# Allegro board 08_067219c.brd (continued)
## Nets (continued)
UNNAMED_17_ICM24512_I159_SCL: A1.6 R61.1
UNNAMED_17_ICM24512_I159_SDA: A1.5 R62.1
UNNAMED_18_7404V6_I276_Y: R135.1 U15.4
UNNAMED_18_ADAU1701_I166_ADCRES: R109.2(N2) U10.3
UNNAMED_18_ADAU1701_I166_CM: C102.1 C104.1 U10.40
UNNAMED_18_ADAU1701_I166_DVDD: C106.P C107.1 C109.1 Q2.3 U10.13 U10.24
UNNAMED_18_ADAU1701_I166_FILTA: C98.1 C100.1 U10.47
UNNAMED_18_ADAU1701_I166_FILTD: C111.1 C113.1 U10.41
UNNAMED_18_ADAU1701_I166_MP6: R110.2(N2) U10.15
UNNAMED_18_ADAU1701_I166_PLLLF: C108.1 C110.1 U10.35
UNNAMED_18_ADAU1701_I166_RESETB: C78.2(N2) R44.1 U10.5
UNNAMED_18_ADAU1701_I166_VDRIVE: Q2.1 R112.1 U10.17
UNNAMED_18_CAP_I169_N2: C108.2(N2) R111.1
UNNAMED_18_CAP_I344_N1: C80.1 P2.2 R51.1
UNNAMED_18_CN2P_I318_N1: P22.1 R113.1
UNNAMED_18_CN10P_I337_N1: P2.1 R77.1
UNNAMED_18_CN10P_I337_N3: P2.3 R78.1
UNNAMED_18_CN10P_I337_N4: P2.4 P44.1(N1) R117.1
UNNAMED_18_CN10P_I337_N5: P2.5 R79.1
UNNAMED_18_CN10P_I337_N6: P2.6 P43.1(N1) R125.1
UNNAMED_18_CN10P_I337_N7: P2.7 R80.1
UNNAMED_18_CN10P_I337_N8: P2.8 R81.1
UNNAMED_18_CN10P_I337_N9: P2.9(N9) R82.1
UNNAMED_18_DIOLED_I280_P: DS4.A(P) R135.2(N2)
UNNAMED_19_CAP_I7_N1: C123.1 R124.2(N2)
UNNAMED_19_CAP_I17_N1: A2.8 C115.1 L17.1 R124.1
UNNAMED_19_CAP_I17_N2: A2.9 C115.2(N2)
UNNAMED_19_CAP_I20_N1: A2.13 C118.1 C122.2(N2) L16.1
UNNAMED_19_CAP_I20_N2: A2.12 C118.2(N2)
UNNAMED_19_CAP_I21_N1: C122.1 R123.2(N2)
UNNAMED_19_CAP_I26_N1: A2.22 C114.1
UNNAMED_19_CAP_I26_N2: A2.23 C114.2(N2) C119.2(N2) L14.1
UNNAMED_19_CAP_I28_N1: A2.18 C121.1
UNNAMED_19_CAP_I28_N2: A2.19 C121.2(N2) L15.1 R122.1
UNNAMED_19_CAP_I32_N2: C129.2(N2) L17.2(N2) P48.1(N1)
UNNAMED_19_CAP_I33_N1: C128.1 L16.2(N2) P47.1(N1)
UNNAMED_19_CAP_I38_N2: C127.2(N2) L15.2(N2) P46.1(N1)
UNNAMED_19_CAP_I40_N1: C120.1 R122.2(N2)
UNNAMED_19_CAP_I42_N1: C119.1 R121.2(N2)
UNNAMED_19_CAP_I44_N1: C126.1 L14.2(N2) P45.1(N1)
UNNAMED_19_CAP_I49_N1: A2.16 C130.1
UNNAMED_19_CAP_I51_N1: A2.6 C90.1 R116.1
UNNAMED_19_CAP_I55_N1: A2.17 C124.1
UNNAMED_19_DIOLED_I16_N: A2.24 DS6.C
UNNAMED_19_DIOLED_I16_P: DS6.A(P) R115.2(N2)
UNNAMED_19_ICBD28623MUV_I18_BCLK: A2.3 R119.2(N2)
UNNAMED_19_ICBD28623MUV_I18_GAIN: A2.5 R83.1 R114.2(N2)
UNNAMED_19_ICBD28623MUV_I18_LRCLK: A2.4 R120.2(N2)
UNNAMED_19_ICBD28623MUV_I18_SDATA: A2.2 R118.2(N2)
USBI_SCL: R77.2(N2) R137.2(N2) U14.4
USBI_SDA: R78.2(N2) R136.2(N2) U12.4
VOUT0: U10.46
VOUT1: U10.45
VOUT2: R89.1 U10.44
VOUT3: R90.1 U10.43(VOUT3)

Pads without a net: U10 31; U15 1

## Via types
v1: diameter 0.508, hole 0.254, TOP to BOTTOM, 1342 vias

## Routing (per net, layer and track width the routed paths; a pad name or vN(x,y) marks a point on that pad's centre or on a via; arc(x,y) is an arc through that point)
DGND: length 1006.2
  TOP w0.203: U10.38 39.39,84.03 C102.2 39.19,84.3 39.42,84.53 U10.37 v1(42.11,84.53) ; C105.2 44.44,87.54 43.74,86.84 U10.33 ; C23.1 43.12,44.31 43.12,45.92 44.2,46.99 U7.30 v1(44.2,50.02) ; v1(45.59,57.02) 45.7,56.92 U7.4 45.7,54.58 v1(45.21,54.09) ; 42.04,48.13 42.2,48.3 U7.26 ; U10.42 39.99,82.03 39.25,81.29 C113.2 ; 47.37,56.9 47.2,56.73 U7.1 47.2,55.52 47.18,55.5 47.18,55.36 v1(46.92,55.11) ; v1(45.47,84.58) 45.24,84.81 U10.30 ; v1(46.99,53.15) 47.16,53.32 U7.44 ; U14.3 v1(62.84,89.01) ; U12.3 v1(62.9,84.31) ; U2.5 14.86,42.84 14.86,42.24 14.66,42.04 v1(14.1,42.04) ; U10.20 50.55,82.53 C99.2 ; U10.7 45.24,76.42 v1(45.47,76.2) ; v1(46.99,50.42) 47.4,50.42 47.5,50.32 U7.38 ; U7.10 42.7,55.34 42.93,55.12 v1(43.1,55.12) ; 52.57,114.74 53.07,115.24 A2.11 ; 52.57,114.74 A2.15 ; 52.57,114.74 v1(52.32,114.49) 52.07,114.74 A2.21 ; 46.14,44.23 46.14,46.05 45.2,46.99 U7.32 v1(45.2,50.02) ; U13.4 18.44,97.91 17.94,98.41 ; U10.1 42.24,78.53 42.04,78.74 v1(42.04,78.75) ; U10.12 v1(48.34,77.6) ; U7.20 v1(41.9,51.82) ; U10.25 v1(48.48,85.96)
  TOP w0.254: v1(11.3,21.72) 11.12,21.53 U8.6
  TOP w0.508: C12.1 55.49,60.96 ; C12.1 54.23,59.91 ; C12.1 52.97,60.96 ; C12.1 54.23,62.01 ; P42.1 8.76,41.31 ; P42.1 7.58,40.13 ; P42.1 8.76,38.95 ; 5.17,23.24 C25.1 ; C25.1 6.22,24.5 ; C25.1 7.28,23.24 ; C25.1 6.22,21.98 ; C107.2 v1(50.8,77.27) ; C107.2 50.22,78.03 ; C107.2 51.38,78.03 ; P40.1 8.76,32.93 ; P40.1 8.76,30.57 ; P40.1 7.58,31.75 ; P40.1 9.94,31.75 ; 40.48,87.63 C103.2 ; C103.2 41.03,87.05 ; C103.2 v1(41.03,88.42) ; R3.1 v1(16.56,38.61) ; R3.1 15.87,39.23 ; R3.1 15.87,37.99 ; C97.N 35.06,87.63 ; C97.N 31.96,87.63 ; C97.N 33.51,86.58 ; C97.N 33.51,88.68 ; 21.4,31.75 C40.1 ; C40.1 22.23,32.91 ; C40.1 22.23,30.59 ; C40.1 23.06,31.75 ; P1.2 34.49,71.48 ; P1.2 34.49,69.11 ; P1.2 35.67,70.29 ; P1.2 33.31,70.29 ; 10.38,59.69 P39.1 ; P39.1 11.56,60.87 ; P39.1 12.74,59.69 ; P39.1 11.56,58.51 ; P21.6 P21.8 59.44,4.78 59.44,6.1 ; 6.25,50.66 C131.1 ; C131.1 7.07,51.82 ; C131.1 5.42,51.82 ; C131.1 6.25,52.97 ; 61.42,112.15 C123.2 ; C123.2 v1(62.23,112.9) ; C123.2 61.42,113.65 ; P1.16 53.45,70.29 ; P1.16 52.27,69.11 ; P1.16 52.27,71.48 ; P1.16 51.09,70.29 ; C79.2 v1(32.85,65.02) ; 29.58,5.28 P27.1 29.58,7.38 ; C65.2 42.37,29.46 ; C65.2 41.78,30 ; C65.2 41.2,29.46 ; C69.2 75.39,85.48 ; C69.2 74.22,85.48 ; C69.2 74.8,84.93 ; P41.1 78.65,38.1 ; P41.1 76.29,38.1 ; P41.1 77.47,36.92 ; P41.1 77.47,39.28 ; P7.1 2.4,118.59 ; P7.1 v1(4.06,116.94) ; P7.1 2.4,115.29 ; 61.25,67.75 P1.23 ; P1.23 62.43,66.57 ; P1.23 62.43,68.94 ; P1.23 63.61,67.75 ; 49.45,25.76 C93.1 ; C93.1 50.62,25.76 ; C93.1 v1(50.04,26.54) ; C62.2 42.24,40 ; C62.2 41.66,40.54 ; C62.2 41.07,40 ; v1(56.13,105.79) C90.2 R42.1 v1(57.15,105.79) ; 46.74,74.8 C78.1 46.01,75.55 ; 37.03,69.11 P1.4 ; P1.4 38.21,70.29 ; P1.4 35.85,70.29 ; P1.4 37.03,71.48 ; C36.1 16.38,50.56 ; C36.1 17.18,49.28 ; C36.1 16.38,47.99 ; P18.2 61.86,81 ; P18.2 63.04,79.82 ; P18.2 61.86,78.64 ; P18.2 60.68,79.82 ; P1.12 47.19,71.48 ; P1.12 48.37,70.29 ; P1.12 46.01,70.29 ; P1.12 47.19,69.11 ; C42.1 v1(14.44,35.18) ; C42.1 15.13,35.76 ; C42.1 15.13,34.59 ; R100.1 54.41,50.6 54.41,49.96 v1(54.23,49.78) ; R100.1 55.24,50.67 ; R100.1 R101.1 55.24,51.82 ; v1(9.16,111.63) C56.2 ; C56.2 9.74,112.4 ; C56.2 8.57,112.4 ; 55.36,74.8 C106.N ; C106.N 58.46,74.8 ; C106.N 56.91,75.86 ; C106.N 56.91,73.75 ; 50.01,9.6 P21.10 ; P21.10 51.16,10.76 ; P21.10 51.16,8.44 ; P21.10 52.32,9.6 ; C126.2 v1(29.72,109.34) ; C126.2 30.92,108.28 ; C126.2 30.92,110.39 ; v1(7.36,87.25) C84.2 ; P5.4 43.86,95.75 ; P5.4 42.68,96.93 ; P5.4 42.68,94.57 ; P5.4 41.5,95.75 ; R5.1 65.96,76.45 ; R5.1 v1(65.39,77.23) ; R5.1 65.39,75.83 ; 36.96,6.1 36.96,4.78 P27.8 P27.6 ; P1.6 39.57,71.48 ; P1.6 39.57,69.11 ; P1.6 40.75,70.29 ; P1.6 38.39,70.29 ; C1.1 12.59,42.14 ; C1.1 v1(9.78,42.14) ; C1.1 11.43,42.97 ; 62.82,86.41 C133.2 ; C133.2 v1(62.82,87.76) ; C133.2 62.27,87 ; C96.N 58.46,87.63 ; C96.N 55.36,87.63 ; C96.N 56.91,86.58 ; C96.N 56.91,88.68 ; 80.64,90.3 A1.4 ; A1.4 81.98,89.74 ; A1.4 81.98,90.86 ; A1.4 v1(83.57,90.3) ; C113.2 v1(39.12,80.53) ; v1(17.17,99.06) C74.2 17.94,98.41 ; 71.46,66.7 DS4.C ; DS4.C 72.26,67.58 ; DS4.C 73.28,66.7 v1(73.28,66.67) ; DS4.C 72.26,65.83 ; 52.37,121.4 C130.2 ; C130.2 v1(52.96,122.15) ; C130.2 53.54,121.4 ; 14.47,58.41 R49.1 15.04,57.78 ; 67.97,66.98 C135.2 ; C135.2 67.97,68.15 ; C135.2 v1(67.18,67.56) ; P2.10 76.11,47.68 ; P2.10 73.87,47.68 ; P2.10 74.99,48.8 ; P2.10 74.99,46.56 ; C3.1 v1(31.5,58.93) ; C44.2 v1(58.16,31.98) ; C64.2 31.48,47.27 ; C64.2 30.9,46.73 ; C64.2 32.07,46.73 ; 12.23,34.7 DS5.C ; DS5.C 13.93,34.7 ; DS5.C v1(13.08,35.75) ; DS5.C 13.08,33.84 ; 38.79,25.76 C31.2 ; C31.2 39.95,25.76 ; C31.2 v1(39.37,26.54) ; C75.2 v1(16.54,93.09) ; 52.06,7.38 P21.1 52.06,5.28 ; C98.2 v1(39.12,77.77) ; R48.1 v1(17.91,42.04) ; TP10.1 81.95,43.81 ; TP10.1 80.77,45 ; TP10.1 79.59,43.81 ; TP10.1 80.77,42.63 ; 58.71,70.29 P1.22 ; P1.22 61.07,70.29 ; P1.22 59.89,71.48 ; P1.22 59.89,69.11 ; v1(22.61,52.82) R31.1 ; C120.2 v1(45.85,120.87) ; 66.67,63.64 U15.3 ; U15.3 67.52,64.2 ; U15.3 v1(65.47,64.2) ; C129.1 74.99,110.39 ; C129.1 74.99,108.28 ; C129.1 v1(76.2,109.34) ; P1.20 58.53,70.29 ; P1.20 57.35,71.48 ; P1.20 57.35,69.11 ; P1.20 56.17,70.29 ; 19.23,19.02 C38.1 ; C38.1 19.23,20.62 ; C38.1 17.95,19.82 ; C38.1 20.51,19.82 ; A1.1 81.98,87.05 ; A1.1 v1(83.57,86.49) ; A1.1 81.98,85.93 ; A1.1 80.64,86.49 ; 47.76,94.57 P5.8 ; P5.8 48.94,95.75 ; P5.8 46.58,95.75 ; P5.8 47.76,96.93 ; 60.94,114.19 R123.1 ; R123.1 60.94,115.43 ; R123.1 v1(61.85,114.81) ; 45.72,24.48 C67.1 ; C67.1 46.3,25.03 ; C67.1 45.14,25.03 ; 81.98,88.47 A1.3 ; A1.3 81.98,89.59 ; A1.3 v1(83.57,89.03) ; A1.3 80.64,89.03 ; R109.1 42.04,76.57 ; R109.1 v1(41.27,75.95) ; R109.1 42.04,75.32 ; v1(65.47,69.03) U9.3 ; U9.3 67.52,69.03 ; U9.3 66.67,68.47 ; 49.12,95.75 P5.10 ; P5.10 50.3,96.93 ; P5.10 51.48,95.75 ; P5.10 50.3,94.57 ; P1.18 55.99,70.29 ; P1.18 53.63,70.29 ; P1.18 54.81,71.48 ; P1.18 54.81,69.11 ; v1(52.2,56.9) v1(52.7,56.9) v1(53.21,56.9) ; C99.2 v1(51.44,82.78) ; 82.04,61.56 TP11.1 ; TP11.1 82.04,63.92 ; TP11.1 83.22,62.74 ; TP11.1 80.86,62.74 ; A3.7 74.95,80.26 C51.2 ; 52.84,94.57 P5.12 ; P5.12 51.66,95.75 ; P5.12 54.02,95.75 ; P5.12 52.84,96.93 ; 20.74,33.04 C41.1 ; C41.1 v1(21.43,33.79) ; C41.1 20.74,34.54 ; R27.1 v1(11.12,14.61) ; 50.8,123.27 C124.2 ; C124.2 50.8,124.87 ; C124.2 49.52,124.07 ; C124.2 52.08,124.07 ; P5.6 46.4,95.75 ; P5.6 45.22,94.57 ; P5.6 44.04,95.75 ; P5.6 45.22,96.93 ; v1(7.38,105.02) R95.2 ; C51.2 75.26,79.99 ; C51.2 74.68,80.54 ; C51.2 v1(73.91,79.99) ; 30.92,117.44 C127.1 ; C127.1 v1(29.72,118.49) ; C127.1 30.92,119.55 ; 61.26,25.76 C94.2 ; C94.2 v1(61.85,26.54) ; C94.2 62.43,25.76 ; R83.2 v1(52.83,105.79) ; C39.1 22.23,26.56 ; C39.1 21.4,25.4 ; C39.1 22.23,24.24 ; C39.1 23.06,25.4 ; 48.55,70.29 P1.14 ; P1.14 49.73,71.48 ; P1.14 50.91,70.29 ; P1.14 49.73,69.11 ; 80.64,87.76 A1.2 ; A1.2 81.98,87.2 ; A1.2 v1(83.57,87.76) ; A1.2 81.98,88.32 ; C109.2 v1(50.8,86.47) ; C109.2 51.38,85.72 ; C109.2 50.22,85.72 ; v1(81.98,75.82) R131.1 ; 57.28,46.3 C66.1 56.74,45.72 ; 26.97,25.76 C32.2 ; C32.2 28.14,25.76 ; C32.2 v1(27.56,26.54) ; C27.1 v1(14.12,20.06) ; C27.1 12.75,20.06 ; C27.1 13.34,19.51 ; C132.1 16.23,56.99 ; C132.1 17.06,55.83 ; C132.1 16.23,54.68 ; P5.2 41.32,95.75 ; P5.2 40.14,94.57 ; P5.2 40.14,96.93 ; P5.2 38.96,95.75 ; 5.28,54.22 DS1.C ; DS1.C 6.13,55.07 ; DS1.C 6.13,53.36 ; C22.1 v1(46.61,43.63) ; C30.1 v1(35.68,31.98) ; C35.1 17.18,52.7 ; C35.1 16.38,51.42 ; C35.1 16.38,53.99 ; 2.4,91.92 P20.1 ; P20.1 3.76,93.57 ; P20.1 2.4,95.23 ; v1(67.18,72.39) C112.2 ; C112.2 67.97,72.97 ; C112.2 67.97,71.81 ; R35.1 22.43,44.56 ; R35.1 v1(22.43,43.05) ; R35.1 23.01,43.94 ; P1.24 63.61,70.29 ; P1.24 62.43,71.48 ; P1.24 61.25,70.29 ; P1.24 62.43,69.11 ; R130.1 v1(86.11,80.26) ; 80.64,82.8 A3.4 ; A3.4 81.98,83.36 ; A3.4 v1(83.53,82.8) ; C63.2 57.28,48.67 ; C63.2 56.69,48.13 ; C63.2 57.86,48.13 ; R41.1 v1(12.32,14.61) ; v1(50.04,53.02) v1(52.07,53.02) ; 74.99,117.44 C128.2 ; C128.2 v1(76.2,118.49) ; C128.2 74.99,119.55 ; P1.10 44.65,71.48 ; P1.10 43.47,70.29 ; P1.10 44.65,69.11 ; P1.10 45.83,70.29 ; C134.2 v1(62.75,92.45) ; C134.2 62.21,91.69 ; C134.2 62.75,91.11 ; R36.1 62.91,44.56 ; R36.1 62.34,43.94 ; R36.1 62.91,43.32 ; R108.1 69.2,4.87 ; R108.1 68.07,4.1 ; R108.1 66.94,4.87 ; R46.1 v1(20.75,35.18) ; C111.2 v1(37.97,80.53) ; C104.2 v1(37.97,85.05) ; C73.2 21.6,96 ; C73.2 v1(22.32,95.45) ; C73.2 21.02,95.45 ; 60.16,53.85 P13.1 ; P13.1 62.52,53.85 ; P13.1 61.34,52.67 ; 21.76,3.82 C87.2 19.65,3.82 ; v1(9.91,126.96) C55.2 ; C55.2 10.49,126.19 ; C55.2 9.32,126.19 ; v1(8.52,87.25) R96.2 ; R28.1 v1(86.11,81.53) ; 40.93,70.29 P1.8 ; P1.8 42.11,71.48 ; P1.8 42.11,69.11 ; P1.8 43.29,70.29 ; C48.1 v1(53.72,31.98) ; C100.2 v1(37.97,77.77) ; C105.2 v1(44.44,88.42) ; v1(39.12,85.05) C102.2 ; R121.1 v1(44.07,114.23) ; v1(42.73,43.63) C23.1 ; v1(22.61,50.16) R32.1 ; C29.2 v1(31.24,31.98) ; v1(8.52,105.02) C83.2
  TOP w0.635: v1(68.07,5.85) R108.1 ; v1(22.73,4.47) E12.1 ; v1(66.04,4.35) E15.1 ; v1(45.21,4.39) E14.1 ; v1(20.7,4.92) C87.2 ; v1(43.56,4.39) E13.1
  L2_GND w0.508: 38.39,70.29 P1.6 ; P1.6 39.57,69.11 ; P1.6 39.57,71.48 ; P1.6 40.75,70.29 ; 74.99,46.56 P2.10 ; P2.10 74.99,48.8 ; P2.10 76.11,47.68 ; P2.10 73.87,47.68 ; 51.66,95.75 P5.12 ; P5.12 52.84,96.93 ; P5.12 52.84,94.57 ; P5.12 54.02,95.75 ; 42.68,94.57 P5.4 ; P5.4 42.68,96.93 ; P5.4 43.86,95.75 ; P5.4 41.5,95.75 ; P21.10 51.16,10.76 ; P21.10 51.16,8.44 ; P21.10 50.01,9.6 ; P21.10 52.32,9.6 ; 54.81,69.11 P1.18 ; P1.18 55.99,70.29 ; P1.18 53.63,70.29 ; P1.18 54.81,71.48 ; 79.59,43.81 TP10.1 ; TP10.1 80.77,45 ; TP10.1 80.77,42.63 ; TP10.1 81.95,43.81 ; 50.3,94.57 P5.10 ; P5.10 50.3,96.93 ; P5.10 51.48,95.75 ; P5.10 49.12,95.75 ; P1.2 34.49,71.48 ; P1.2 34.49,69.11 ; P1.2 35.67,70.29 ; P1.2 33.31,70.29 ; 61.25,67.75 P1.23 ; P1.23 62.43,66.57 ; P1.23 62.43,68.94 ; P1.23 63.61,67.75 ; 82.04,61.56 TP11.1 ; TP11.1 80.86,62.74 ; TP11.1 82.04,63.92 ; TP11.1 83.22,62.74 ; 44.65,69.11 P1.10 ; P1.10 43.47,70.29 ; P1.10 44.65,71.48 ; P1.10 45.83,70.29 ; P5.6 45.22,96.93 ; P5.6 46.4,95.75 ; P5.6 45.22,94.57 ; P5.6 44.04,95.75 ; P1.20 57.35,71.48 ; P1.20 58.53,70.29 ; P1.20 56.17,70.29 ; P1.20 57.35,69.11 ; P5.2 40.14,96.93 ; P5.2 41.32,95.75 ; P5.2 38.96,95.75 ; P5.2 40.14,94.57 ; P1.24 62.43,71.48 ; P1.24 63.61,70.29 ; P1.24 61.25,70.29 ; P1.24 62.43,69.11 ; 29.58,5.28 P27.1 29.58,7.38 ; 8.76,30.57 P40.1 ; P40.1 8.76,32.93 ; P40.1 9.94,31.75 ; P40.1 7.58,31.75 ; 51.09,70.29 P1.16 ; P1.16 53.45,70.29 ; P1.16 52.27,69.11 ; P1.16 52.27,71.48 ; 47.19,69.11 P1.12 ; P1.12 48.37,70.29 ; P1.12 47.19,71.48 ; P1.12 46.01,70.29 ; 8.76,38.95 P42.1 ; P42.1 7.58,40.13 ; P42.1 8.76,41.31 ; P42.1 9.94,40.13 ; 60.16,53.85 P13.1 ; P13.1 62.52,53.85 ; P13.1 61.34,52.67 ; 46.58,95.75 P5.8 ; P5.8 47.76,96.93 ; P5.8 47.76,94.57 ; P5.8 48.94,95.75 ; P41.1 78.65,38.1 ; P41.1 76.29,38.1 ; P41.1 77.47,36.92 ; P41.1 77.47,39.28 ; P1.8 42.11,71.48 ; P1.8 43.29,70.29 ; P1.8 42.11,69.11 ; P1.8 40.93,70.29 ; 52.06,5.28 P21.1 52.06,7.38 ; 10.38,59.69 P39.1 ; P39.1 12.74,59.69 ; P39.1 11.56,58.51 ; P39.1 11.56,60.87 ; 59.89,69.11 P1.22 ; P1.22 61.07,70.29 ; P1.22 59.89,71.48 ; P1.22 58.71,70.29 ; P1.4 37.03,71.48 ; P1.4 38.21,70.29 ; P1.4 37.03,69.11 ; P1.4 35.85,70.29 ; 48.55,70.29 P1.14 ; P1.14 49.73,71.48 ; P1.14 49.73,69.11 ; P1.14 50.91,70.29 ; P21.6 P21.8 59.44,4.78 59.44,6.1 ; 36.96,6.1 36.96,4.78 P27.8 P27.6 ; 60.68,79.82 P18.2 ; P18.2 61.86,81 ; P18.2 61.86,78.64 ; P18.2 63.04,79.82
  L3_PWR w0.508: 11.56,58.51 P39.1 ; P39.1 11.56,60.87 ; P39.1 12.74,59.69 ; P39.1 10.38,59.69 ; 54.81,69.11 P1.18 ; P1.18 53.63,70.29 ; P1.18 54.81,71.48 ; 34.49,69.11 P1.2 ; P1.2 34.49,71.48 ; P1.2 33.31,70.29 ; 56.17,70.29 P1.20 57.35,69.11 ; TP10.1 81.95,43.81 ; TP10.1 80.77,42.63 ; TP10.1 79.59,43.81 ; 47.76,96.93 P5.8 47.76,94.57 ; P1.14 49.73,71.48 ; P1.14 50.91,70.29 ; P1.14 49.73,69.11 ; P5.12 54.02,95.75 ; P5.12 52.84,96.93 ; P5.12 52.84,94.57 ; P41.1 77.47,39.28 ; P41.1 76.29,38.1 ; P41.1 78.65,38.1 ; P41.1 77.47,36.92 ; 38.39,70.29 P1.6 ; P1.6 39.57,69.11 ; P1.6 39.57,71.48 ; 48.37,70.29 P1.12 47.19,69.11 ; 51.09,70.29 P1.16 ; P1.16 52.27,71.48 ; P1.16 53.45,70.29 ; P1.16 52.27,69.11 ; 60.68,79.82 P18.2 ; P18.2 61.86,78.64 ; P18.2 61.86,81 ; 40.14,94.57 P5.2 ; P5.2 38.96,95.75 ; P5.2 40.14,96.93 ; P13.1 62.52,53.85 ; 45.22,94.57 P5.6 45.22,96.93 ; 42.68,94.57 P5.4 42.68,96.93 ; P21.6 P21.8 ; 50.3,94.57 P5.10 ; P5.10 51.48,95.75 ; P5.10 50.3,96.93 ; 59.89,69.11 P1.22 ; P1.22 59.89,71.48 ; P1.22 61.07,70.29 ; 37.03,69.11 P1.4 38.21,70.29 ; P27.6 P27.8
  L4_PWR w0.508: P21.6 P21.8 ; P27.6 P27.8
  L5_GND w0.508: P5.6 46.4,95.75 ; P5.6 45.22,94.57 ; P5.6 45.22,96.93 ; P5.6 44.04,95.75 ; 7.58,40.13 P42.1 ; P42.1 9.94,40.13 ; P42.1 8.76,41.31 ; P42.1 8.76,38.95 ; 11.56,58.51 P39.1 ; P39.1 10.38,59.69 ; P39.1 12.74,59.69 ; P39.1 11.56,60.87 ; P1.20 58.53,70.29 ; P1.20 56.17,70.29 ; P1.20 57.35,69.11 ; P1.20 57.35,71.48 ; P2.10 76.11,47.68 ; P2.10 74.99,48.8 ; P2.10 73.87,47.68 ; P2.10 74.99,46.56 ; P1.8 43.29,70.29 ; P1.8 42.11,69.11 ; P1.8 42.11,71.48 ; P1.8 40.93,70.29 ; P1.4 37.03,71.48 ; P1.4 37.03,69.11 ; P1.4 35.85,70.29 ; P1.4 38.21,70.29 ; 48.55,70.29 P1.14 ; P1.14 49.73,69.11 ; P1.14 50.91,70.29 ; P1.14 49.73,71.48 ; P5.8 48.94,95.75 ; P5.8 47.76,94.57 ; P5.8 47.76,96.93 ; P5.8 46.58,95.75 ; 47.19,69.11 P1.12 ; P1.12 48.37,70.29 ; P1.12 47.19,71.48 ; P1.12 46.01,70.29 ; P1.22 59.89,71.48 ; P1.22 59.89,69.11 ; P1.22 61.07,70.29 ; P1.22 58.71,70.29 ; P1.10 44.65,71.48 ; P1.10 44.65,69.11 ; P1.10 43.47,70.29 ; P1.10 45.83,70.29 ; P5.4 43.86,95.75 ; P5.4 41.5,95.75 ; P5.4 42.68,94.57 ; P5.4 42.68,96.93 ; P1.2 35.67,70.29 ; P1.2 34.49,69.11 ; P1.2 33.31,70.29 ; P1.2 34.49,71.48 ; P1.18 55.99,70.29 ; P1.18 54.81,71.48 ; P1.18 54.81,69.11 ; P1.18 53.63,70.29 ; P40.1 8.76,32.93 ; P40.1 9.94,31.75 ; P40.1 8.76,30.57 ; P40.1 7.58,31.75 ; P41.1 78.65,38.1 ; P41.1 77.47,39.28 ; P41.1 77.47,36.92 ; P41.1 76.29,38.1 ; 29.58,7.38 P27.1 29.58,5.28 ; P18.2 61.86,81 ; P18.2 60.68,79.82 ; P18.2 63.04,79.82 ; P18.2 61.86,78.64 ; 62.43,69.11 P1.24 ; P1.24 62.43,71.48 ; P1.24 61.25,70.29 ; P1.24 63.61,70.29 ; 39.57,69.11 P1.6 ; P1.6 40.75,70.29 ; P1.6 39.57,71.48 ; P1.6 38.39,70.29 ; 82.04,61.56 TP11.1 ; TP11.1 82.04,63.92 ; TP11.1 80.86,62.74 ; TP11.1 83.22,62.74 ; 50.01,9.6 P21.10 ; P21.10 52.32,9.6 ; P21.10 51.16,8.44 ; P21.10 51.16,10.76 ; TP10.1 81.95,43.81 ; TP10.1 79.59,43.81 ; TP10.1 80.77,42.63 ; TP10.1 80.77,45 ; 52.06,5.28 P21.1 52.06,7.38 ; 60.16,53.85 P13.1 ; P13.1 62.52,53.85 ; P13.1 61.34,52.67 ; P1.16 52.27,71.48 ; P1.16 52.27,69.11 ; P1.16 51.09,70.29 ; P1.16 53.45,70.29 ; 38.96,95.75 P5.2 ; P5.2 41.32,95.75 ; P5.2 40.14,94.57 ; P5.2 40.14,96.93 ; 62.43,66.57 P1.23 ; P1.23 63.61,67.75 ; P1.23 62.43,68.94 ; P1.23 61.25,67.75 ; 36.96,6.1 36.96,4.78 P27.8 P27.6 ; P5.10 51.48,95.75 ; P5.10 49.12,95.75 ; P5.10 50.3,96.93 ; P5.10 50.3,94.57 ; P21.6 P21.8 59.44,4.78 59.44,6.1 ; 52.84,94.57 P5.12 ; P5.12 51.66,95.75 ; P5.12 54.02,95.75 ; P5.12 52.84,96.93
  BOTTOM w0.508: P13.1 62.52,53.85 ; P13.1 60.16,53.85 ; P13.1 61.34,52.67 ; 49.12,95.75 P5.10 ; P5.10 50.3,96.93 ; P5.10 51.48,95.75 ; 39.82,114.94 C117.2 ; C117.2 41.47,112.14 ; C117.2 41.47,117.73 ; C117.2 43.12,114.94 ; P1.2 35.67,70.29 ; P1.2 34.49,71.48 ; P1.2 33.31,70.29 ; 46.46,43.78 C22.1 46.49,44.58 ; P40.1 8.76,32.93 ; P40.1 7.58,31.75 ; P40.1 9.94,31.75 ; P40.1 8.76,30.57 ; v1(45.26,59.94) 45.26,59.97 45.26,59.97 45.2,59.91 C2.2 C4.1 45.2,57.42 v1(45.59,57.02) ; P1.6 40.75,70.29 ; P1.6 38.39,70.29 ; P1.6 39.57,71.48 ; v1(41.9,51.82) 42,51.91 C17.1 ; 22.86,6.67 L3.2 ; L3.2 22.86,8.09 ; L3.2 23.8,7.38 ; L3.2 21.92,7.38 ; P1.4 37.03,71.48 ; P1.4 35.85,70.29 ; P1.4 38.21,70.29 ; P41.1 78.65,38.1 ; P41.1 76.29,38.1 ; P41.1 77.47,39.28 ; P41.1 77.47,36.92 ; 71.16,8.48 D4.A ; D4.A v1(72.9,8.48) ; D4.A 71.87,9.34 ; D4.A 71.87,7.62 ; P5.12 52.84,96.93 ; P5.12 54.02,95.75 ; P5.12 51.66,95.75 ; 45.37,48.89 C89.1 ; C89.1 44.83,49.4 ; C89.1 45.37,49.91 ; 61.25,70.29 P1.24 ; P1.24 62.43,71.48 ; P1.24 62.43,69.11 ; 82.04,61.56 TP11.1 ; TP11.1 82.04,63.92 ; TP11.1 80.86,62.74 ; TP11.1 83.22,62.74 ; C53.2 64.72,6.5 ; C53.2 64.14,5.95 ; C53.2 63.55,6.5 ; 42.88,43.78 C23.1 42.86,44.58 ; 47.9,52.05 C19.2 ; C19.2 48.48,52.6 ; C19.2 47.32,52.6 ; 51.09,70.29 P1.16 ; P1.16 53.45,70.29 ; P1.16 52.27,71.48 ; 61.25,67.75 P1.23 ; P1.23 62.43,68.94 ; P1.23 63.61,67.75 ; 8.76,38.95 P42.1 ; P42.1 9.94,40.13 ; P42.1 7.58,40.13 ; P42.1 8.76,41.31 ; 74.99,46.56 P2.10 ; P2.10 76.11,47.68 ; P2.10 73.87,47.68 ; P5.8 48.94,95.75 ; P5.8 47.76,96.93 ; P5.8 46.58,95.75 ; 58.71,70.29 P1.22 59.89,71.48 ; 62.51,119.6 C125.1 ; C125.1 64.16,122.4 ; C125.1 65.81,119.6 ; C125.1 64.16,116.81 ; v1(46.92,55.11) 46.92,55.34 46.41,55.85 C13.2 C14.2 ; 36.33,11.94 R140.2 ; R140.2 37.88,11.94 ; R140.2 37.11,13.07 ; R140.2 37.11,10.81 ; 44.45,55.85 C14.2 ; C14.2 44.96,56.39 ; 44.04,95.75 P5.6 ; P5.6 46.4,95.75 ; P5.6 45.22,96.93 ; C43.1 48.26,42.2 ; C43.1 47,41.15 ; C43.1 48.26,40.09 ; C43.1 49.52,41.15 ; 48.55,70.29 P1.14 ; P1.14 50.91,70.29 ; P1.14 49.73,71.48 ; v1(43.69,54.09) 43.69,54.34 43.81,54.45 C16.2 ; P5.4 42.68,96.93 ; P5.4 43.86,95.75 ; P5.4 41.5,95.75 ; C85.1 43.66,49.91 ; C85.1 43.66,48.89 ; C85.1 44.19,49.4 ; 69.02,3.46 R45.2 ; R45.2 69.02,5.37 ; R45.2 68.25,4.42 ; R45.2 v1(70.1,4.42) ; 41.07,53.22 C15.2 ; C15.2 41.76,53.33 v1(42.93,53.33) ; C15.2 42.24,53.22 ; C15.2 41.66,52.67 ; 46.01,70.29 P1.12 ; P1.12 48.37,70.29 ; P1.12 47.19,71.48 ; 42.35,60.84 42.8,60.84 C8.1 ; 42.35,60.84 v1(42.35,59.94) ; 42.35,60.84 41.91,60.84 C6.1 C5.1 40.51,60.84 v1(39.75,60.84) ; 52.06,5.28 P21.1 52.06,7.38 ; v1(52.07,53.02) C7.2 53.54,53.6 C10.1 ; 60.68,79.82 P18.2 ; P18.2 61.86,78.64 ; P18.2 61.86,81 ; P1.10 45.83,70.29 ; P1.10 44.65,71.48 ; P1.10 43.47,70.29 ; 79.59,43.81 TP10.1 ; TP10.1 80.77,42.63 ; TP10.1 81.95,43.81 ; P1.20 57.35,71.48 ; P1.20 56.17,70.29 ; P1.20 58.53,70.29 ; C8.1 43.51,60.71 ; C8.1 42.93,60.17 ; L12.2 45.34,8.09 ; L12.2 45.34,6.67 ; L12.2 44.4,7.38 ; L12.2 46.28,7.38 ; P27.6 P27.8 36.96,4.78 36.96,6.1 ; 62.51,113.66 C116.2 ; C116.2 64.16,116.46 ; C116.2 65.81,113.66 ; C116.2 64.16,110.87 ; P1.18 54.81,71.48 ; P1.18 53.63,70.29 ; P1.18 55.99,70.29 ; R143.2 64.24,14.59 ; R143.2 63.46,13.46 ; R143.2 64.24,12.33 ; R143.2 65.01,13.46 ; C16.2 44.35,55.88 ; C16.2 43.81,56.46 ; P5.2 40.14,96.93 ; P5.2 38.96,95.75 ; P5.2 41.32,95.75 ; 39.89,41.15 C86.1 ; C86.1 41.15,40.09 ; C86.1 41.15,42.2 ; C86.1 42.41,41.15 ; C80.2 v1(72.99,59.69) ; 10.38,59.69 P39.1 ; P39.1 12.74,59.69 ; P39.1 11.56,58.51 ; P39.1 11.56,60.87 ; 40.93,70.29 P1.8 ; P1.8 42.11,71.48 ; P1.8 43.29,70.29 ; C11.2 v1(50.04,53.02) ; 73.91,16.97 C92.1 73.41,17.5 ; C17.1 42.29,52.45 ; C17.1 42.8,51.91 ; 29.58,5.28 P27.1 29.58,7.38 ; 50.01,9.6 P21.10 51.16,8.44 ; P21.6 P21.8 59.44,4.78 59.44,6.1 ; v1(41.5,77.06) 41.52,77.08 C101.2 ; 24.27,6.74 R141.1 ; R141.1 24.89,6.17 ; R141.1 25.51,6.74 ; 54.67,12.52 D7.A 53.96,11.66 ; C101.2 42.07,77.72 ; C101.2 41.52,78.31 ; C9.1 51.05,53.02
  vias: v1(2.54,114.94) v1(2.54,112.39) v1(2.54,109.86) v1(2.54,107.31) v1(2.54,104.77) v1(2.54,102.23) v1(2.54,89.53) v1(2.54,87) v1(2.54,84.45) v1(2.54,81.91) v1(2.54,79.38) v1(2.54,76.83) v1(2.54,66.67) v1(2.54,61.59) v1(2.54,41.27) v1(2.54,38.73) v1(2.54,33.66) v1(2.54,28.58) v1(2.54,20.95) v1(2.54,18.41) v1(2.54,15.88) v1(2.54,13.34) v1(2.54,10.79) v1(3.96,92.81) v1(4.06,70.71) v1(5.08,117.47) v1(5.08,114.94) v1(5.08,112.39) v1(5.08,109.86) v1(5.08,107.31) v1(5.08,104.77) v1(5.08,94.61) v1(5.08,92.08) v1(5.08,89.53) v1(5.08,87) v1(5.08,84.45) v1(5.08,81.91) v1(5.08,71.75) v1(5.08,69.22) v1(5.08,66.67) v1(5.08,61.59) v1(5.08,54.86) v1(5.08,54.23) v1(5.08,53.59) v1(5.08,41.27) v1(5.08,38.73) v1(5.08,33.66) v1(5.08,28.58) v1(5.08,20.95) v1(5.08,18.41) v1(5.08,15.88) v1(5.08,13.34) v1(5.08,10.79) v1(5.21,52.45) v1(5.21,51.82) v1(5.21,51.18) v1(5.59,24.77) v1(5.59,21.72) v1(7.38,82.16) v1(7.36,64.39) v1(7.62,122.55) v1(7.62,120.02) v1(7.62,117.47) v1(7.62,114.94) v1(7.62,112.39) v1(7.62,109.86) v1(7.62,107.31) v1(7.62,102.23) v1(7.62,99.69) v1(7.62,97.16) v1(7.62,94.61) v1(7.62,84.45) v1(7.62,79.38) v1(7.62,76.83) v1(7.62,74.3) v1(7.62,71.75) v1(7.62,61.59) v1(7.62,41.27) v1(7.62,38.73) v1(7.62,33.66) v1(7.62,28.58) v1(7.62,20.95) v1(7.62,18.41) v1(7.62,15.88) v1(7.62,13.34) v1(7.62,10.79) v1(8.52,82.16) v1(8.52,64.39) v1(10.03,19.56) v1(10.16,135.26) v1(10.16,132.72) v1(10.16,114.94) v1(10.16,112.39) v1(10.16,109.86) v1(10.16,107.31) v1(10.16,104.77) v1(10.16,102.23) v1(10.16,99.69) v1(10.16,87) v1(10.16,84.45) v1(10.16,81.91) v1(10.16,79.38) v1(10.16,76.83) v1(10.16,64.14) v1(10.16,61.59) v1(10.16,33.66) v1(10.16,28.58) v1(10.16,10.79) v1(10.16,5.71) v1(10.16,3.17) v1(10.79,19.56) v1(11.56,19.56) v1(12.7,135.26) v1(12.7,132.72) v1(12.7,130.18) v1(12.7,125.09) v1(12.7,122.55) v1(12.7,120.02) v1(12.7,114.94) v1(12.7,109.86) v1(12.7,107.31) v1(12.7,104.77) v1(12.7,99.69) v1(12.7,97.16) v1(12.7,87) v1(12.7,84.45) v1(12.7,81.91) v1(12.7,76.83) v1(12.7,74.3) v1(12.7,64.14) v1(12.7,61.59) v1(12.7,13.34) v1(12.7,10.79) v1(12.7,8.25) v1(12.7,5.71) v1(12.7,3.17) v1(14.61,10.79) v1(14.61,8.25) v1(14.61,5.71) v1(14.61,3.17) v1(15.24,135.26) v1(15.24,132.72) v1(15.24,130.18) v1(15.24,127.64) v1(15.24,125.09) v1(15.24,122.55) v1(15.24,120.02) v1(15.24,117.47) v1(15.24,114.94) v1(15.24,109.86) v1(15.24,107.31) v1(15.24,104.77) v1(15.24,97.16) v1(15.24,94.61) v1(15.24,87) v1(15.24,84.45) v1(15.24,81.91) v1(15.24,64.14) v1(15.24,61.59) v1(15.24,59.05) v1(15.24,13.34) v1(15.49,42.8) v1(15.62,58.17) v1(15.62,57.53) v1(16.54,70.23) v1(17.02,13.72) v1(17.17,76.2) v1(17.27,56.52) v1(17.27,55.88) v1(17.27,55.24) v1(17.42,53.39) v1(17.42,52.75) v1(17.42,52.12) v1(17.42,49.96) v1(17.42,49.32) v1(17.42,48.69) v1(17.78,135.26) v1(17.78,132.72) v1(17.78,130.18) v1(17.78,127.64) v1(17.78,125.09) v1(17.78,122.55) v1(17.78,120.02) v1(17.78,117.47) v1(17.78,114.94) v1(17.78,109.86) v1(17.78,107.31) v1(17.78,104.77) v1(17.78,97.16) v1(17.78,94.61) v1(17.78,87) v1(17.78,84.45) v1(17.78,81.91) v1(17.78,71.75) v1(17.78,64.14) v1(17.78,61.59) v1(17.78,59.05) v1(17.78,57.53) v1(17.78,15.88) v1(17.91,55.88) v1(17.91,54.23) v1(17.91,52.58) v1(17.91,51.05) v1(18.43,96.01) v1(18.43,73.15) v1(18.64,18.78) v1(19.19,96.01) v1(19.18,55.88) v1(19.18,54.23) v1(19.18,52.7) v1(19.18,51.05) v1(19.18,48.89) v1(19.28,18.78) v1(19.69,16.38) v1(19.91,18.78) v1(19.95,96.01) v1(19.95,73.15) v1(20.07,50.04) v1(20.19,51.69) v1(20.32,135.26) v1(20.32,132.72) v1(20.32,130.18) v1(20.32,127.64) v1(20.32,125.09) v1(20.32,122.55) v1(20.32,120.02) v1(20.32,117.47) v1(20.32,114.94) v1(20.32,109.86) v1(20.32,107.31) v1(20.32,104.77) v1(20.32,84.45) v1(20.32,81.91) v1(20.32,79.38) v1(20.32,47.88) v1(21.97,60.2) v1(22.1,48.26) v1(22.32,72.59) v1(22.35,19.05) v1(22.72,22.88) v1(22.86,135.26) v1(22.86,132.72) v1(22.86,130.18) v1(22.86,125.09) v1(22.86,122.55) v1(22.86,120.02) v1(22.86,117.47) v1(22.86,109.86) v1(22.86,107.31) v1(22.86,104.77) v1(22.86,102.23) v1(22.86,99.69) v1(22.86,97.16) v1(22.86,94.61) v1(22.86,92.08) v1(22.86,89.53) v1(22.86,87) v1(22.86,81.91) v1(22.86,79.38) v1(22.86,74.3) v1(22.86,71.75) v1(22.86,66.67) v1(22.86,20.95) v1(22.86,8.51) v1(23.23,22.88) v1(23.27,32.43) v1(23.27,31.8) v1(23.27,31.16) v1(23.27,26.08) v1(23.27,25.45) v1(23.27,24.81) v1(23.49,54.61) v1(23.62,47.62) v1(23.88,70.36) v1(24.26,53.72) v1(24.38,48.13) v1(24.77,38.35) v1(24.77,34.92) v1(24.77,30.86) v1(24.77,28.07) v1(24.77,25.53) v1(24.77,22.73) v1(24.89,5.59) v1(25.02,53.72) v1(25.27,51.56) v1(25.27,50.29) v1(25.4,87) v1(25.4,84.45) v1(25.4,81.91) v1(25.4,76.83) v1(25.4,74.3) v1(25.4,69.22) v1(25.4,66.67) v1(25.4,41.27) v1(25.4,36.2) v1(25.4,33.66) v1(25.53,71.88) v1(25.78,40.39) v1(26.16,54.23) v1(26.16,47.62) v1(26.8,51.31) v1(26.8,50.55) v1(27.18,53.85) v1(27.43,45.09) v1(27.69,52.2) v1(27.94,135.26) v1(27.94,132.72) v1(27.94,122.55) v1(27.94,120.02) v1(27.94,114.94) v1(27.94,112.39) v1(27.94,109.86) v1(27.94,92.08) v1(27.94,89.53) v1(27.94,84.45) v1(27.94,81.91) v1(27.94,79.38) v1(27.94,76.83) v1(27.94,74.3) v1(27.94,71.75) v1(27.94,41.27) v1(27.94,38.73) v1(27.94,36.2) v1(27.94,33.66) v1(27.94,31.12) v1(27.94,28.58) v1(29.08,59.56) v1(29.34,51.56) v1(29.34,47.62) v1(29.97,35.94) v1(30.23,59.69) v1(30.48,114.94) v1(30.48,112.39) v1(30.48,92.08) v1(30.48,89.53) v1(30.48,87) v1(30.48,84.45) v1(30.48,81.91) v1(30.48,79.38) v1(30.48,76.83) v1(30.48,74.3) v1(30.48,69.22) v1(30.48,66.67) v1(30.48,64.14) v1(30.48,38.73) v1(30.73,51.56) v1(30.73,50.36) v1(30.99,22.86) v1(30.99,21.21) v1(30.99,19.69) v1(30.99,18.16) v1(30.99,16.64) v1(30.99,15.11) v1(30.99,13.59) v1(31.24,88.13) v1(31.24,87.62) v1(31.24,87.11) v1(31.37,60.58) v1(31.37,38.73) v1(31.37,33.66) v1(31.37,31.12) v1(31.37,29.84) v1(31.37,28.58) v1(31.37,27.3) v1(31.43,62.74) v1(31.75,88.13) v1(31.75,87.62) v1(31.75,87.11) v1(31.75,41.27) v1(32.64,51.56) v1(32.64,50.36) v1(32.7,42.65) v1(33.02,114.94) v1(33.02,112.39) v1(33.02,92.08) v1(33.02,89.53) v1(33.02,84.45) v1(33.02,81.91) v1(33.02,79.38) v1(33.02,76.83) v1(33.02,74.3) v1(33.02,69.22) v1(34.04,60.77) v1(34.23,43.79) v1(35.3,45.74) v1(35.56,114.94) v1(35.56,112.39) v1(35.56,92.08) v1(35.56,89.53) v1(35.56,84.45) v1(35.56,81.91) v1(35.56,76.83) v1(35.56,74.3) v1(35.56,40.64) v1(35.56,38.73) v1(35.56,33.66) v1(35.56,31.12) v1(35.56,29.84) v1(35.56,28.58) v1(35.56,27.3) v1(35.93,22.86) v1(35.93,21.21) v1(35.93,19.69) v1(35.93,18.16) v1(35.93,16.64) v1(35.93,15.11) v1(35.93,13.59) v1(36.13,43.95) v1(36.53,41.27) v1(36.64,72.58) v1(36.95,35.94) v1(37.21,51.69) v1(37.46,61.09) v1(37.97,72.64) v1(38.1,135.26) v1(38.1,132.72) v1(38.1,94.61) v1(38.1,92.08) v1(38.1,89.53) v1(38.03,44.06) v1(38.1,33.66) v1(38.1,31.12) v1(38.1,28.58) v1(38.1,20.95) v1(38.43,41.37) v1(38.48,70.99) v1(38.48,13.46) v1(38.54,61.28) v1(38.93,62.1) v1(38.86,44.83) v1(39.12,75.31) v1(39.37,76.83) v1(39.62,116.33) v1(39.62,113.16) v1(40.32,69.02) v1(40.26,42.42) v1(40.39,75.31) v1(40.51,71.37) v1(40.64,135.26) v1(40.64,132.72) v1(40.64,130.18) v1(40.64,127.64) v1(40.64,125.09) v1(40.64,102.23) v1(40.64,99.69) v1(40.64,97.16) v1(40.64,33.66) v1(40.64,31.12) v1(40.64,23.49) v1(40.64,20.95) v1(41.21,104.14) v1(41.27,97.92) v1(41.34,100.84) v1(41.47,69.02) v1(42.03,17.78) v1(42.23,106.62) v1(42.48,101.47) v1(42.55,98.81) v1(42.8,44.97) v1(42.86,68.96) v1(42.93,54.09) v1(42.93,52.57) v1(42.93,51.81) v1(42.93,51.04) v1(43.12,71.31) v1(43.18,135.26) v1(43.18,132.72) v1(43.18,130.18) v1(43.18,127.64) v1(43.18,125.09) v1(43.18,122.55) v1(43.18,104.77) v1(43.18,103.31) v1(43.18,102.23) v1(43.18,99.69) v1(43.18,97.16) v1(43.18,33.66) v1(43.18,23.49) v1(43.18,20.95) v1(43.43,100.97) v1(43.69,98.93) v1(43.69,53.33) v1(43.69,52.57) v1(43.69,51.81) v1(43.69,51.04) v1(43.81,97.92) v1(44.01,69.02) v1(44.45,106.17) v1(44.45,99.82) v1(44.45,54.09) v1(44.45,53.33) v1(44.45,52.57) v1(44.45,51.81) v1(44.45,51.04) v1(44.96,98.42) v1(45.21,100.58) v1(45.21,53.33) v1(45.21,52.57) v1(45.21,51.81) v1(45.21,51.04) v1(45.28,69.02) v1(45.3,39.97) v1(45.34,8.51) v1(45.47,81.15) v1(45.72,135.26) v1(45.72,132.72) v1(45.72,130.18) v1(45.72,127.64) v1(45.72,125.09) v1(45.72,122.55) v1(45.72,107.31) v1(45.72,98.42) v1(45.72,97.16) v1(45.72,82.17) v1(45.72,31.75) v1(45.72,23.49) v1(45.72,20.95) v1(45.85,101.22) v1(45.97,91.31) v1(45.97,54.09) v1(45.97,53.33) v1(45.97,52.57) v1(45.97,51.81) v1(45.97,51.04) v1(46.1,99.69) v1(46.42,69.02) v1(46.48,101.85) v1(46.48,18.41) v1(46.54,44.97) v1(46.74,100.33) v1(46.86,108.46) v1(46.86,99.31) v1(46.93,78.99) v1(46.86,74.04) v1(46.99,41.91) v1(47.18,91.12) v1(47.24,102.62) v1(47.24,97.16) v1(47.24,84.58) v1(47.24,83.31) v1(47.24,81.41) v1(47.37,100.97) v1(47.5,21.54) v1(47.56,109.28) v1(47.62,36.83) v1(47.62,33.66) v1(47.62,31.75) v1(47.75,100.2) v1(47.75,97.92) v1(48.13,101.73) v1(48.26,135.26) v1(48.26,132.72) v1(48.26,130.18) v1(48.26,127.64) v1(48.26,125.09) v1(48.26,122.55) v1(48.26,97.16) v1(48.26,75.56) v1(48.26,74.17) v1(48.26,23.49) v1(48.39,88.27) v1(48.39,87.38) v1(48.51,100.97) v1(48.45,89.28) v1(48.7,99.19) v1(48.64,72.64) v1(48.89,39.37) v1(49.29,42.27) v1(49.4,101.85) v1(49.66,89.92) v1(49.66,88.9) v1(49.66,87.76) v1(49.66,75.31) v1(49.66,73.79) v1(49.78,97.92) v1(49.91,108.97) v1(49.91,105.28) v1(49.91,100.46) v1(50.04,86.87) v1(50.16,29.84) v1(50.16,27.94) v1(50.29,108.33) v1(50.42,104.01) v1(50.42,44.96) v1(50.55,103) v1(50.55,101.22) v1(50.8,135.26) v1(50.8,132.72) v1(50.8,130.18) v1(50.8,127.64) v1(50.8,125.09) v1(50.8,98.42) v1(50.8,97.16) v1(50.8,38.73) v1(50.8,36.83) v1(50.97,41.37) v1(51.18,104.52) v1(51.37,44.06) v1(51.43,102.23) v1(51.56,115.25) v1(51.56,114.49) v1(51.56,113.73) v1(52.07,100.58) v1(52.32,115.25) v1(52.32,113.73) v1(52.32,97.92) v1(52.45,102.81) v1(52.45,35.94) v1(52.58,104.33) v1(52.87,41.27) v1(52.96,101.47) v1(53.09,115.25) v1(53.09,114.49) v1(53.09,113.73) v1(53.27,43.95) v1(53.34,135.26) v1(53.34,132.72) v1(53.34,130.18) v1(53.34,127.64) v1(53.34,125.09) v1(53.34,89.53) v1(53.4,12.38) v1(53.4,11.87) v1(53.4,11.37) v1(53.4,10.86) v1(53.47,22.86) v1(53.47,21.21) v1(53.47,19.69) v1(53.47,18.16) v1(53.47,16.64) v1(53.47,15.11) v1(53.47,13.59) v1(53.72,78.36) v1(53.78,102.49) v1(53.85,104.33) v1(53.84,40.64) v1(53.84,38.73) v1(53.85,33.66) v1(53.85,31.12) v1(53.85,29.84) v1(53.85,28.58) v1(53.85,27.3) v1(54.61,101.6) v1(54.86,97.92) v1(55.12,49.78) v1(55.17,43.79) v1(55.24,96.52) v1(55.24,93.98) v1(55.24,92.08) v1(55.37,101.6) v1(55.37,89.53) v1(55.37,85.98) v1(55.44,100.27) v1(55.44,98.74) v1(55.69,61.34) v1(55.69,60.83) v1(55.69,60.39) v1(55.88,135.26) v1(55.88,132.72) v1(55.88,130.18) v1(55.88,127.64) v1(55.88,125.09) v1(55.88,122.55) v1(55.88,71.75) v1(56.13,103.89) v1(56.39,45.72) v1(56.71,105.16) v1(56.64,102.49) v1(56.64,100.46) v1(56.71,98.68) v1(56.64,96.52) v1(56.64,93.98) v1(56.64,91.95) v1(56.64,89.53) v1(56.64,85.85) v1(56.64,83.57) v1(56.64,82.3) v1(56.7,42.65) v1(56.77,76.83) v1(56.77,72.77) v1(57.4,97.92) v1(57.66,103.57) v1(57.65,41.27) v1(58.04,80.64) v1(58.04,77.91) v1(58.03,38.73) v1(58.04,33.66) v1(58.04,31.12) v1(58.03,29.84) v1(58.03,28.58) v1(58.03,27.3) v1(58.17,82.23) v1(58.42,135.26) v1(58.42,132.72) v1(58.42,130.18) v1(58.42,127.64) v1(58.42,125.09) v1(58.42,107.31) v1(58.42,94.61) v1(58.42,92.08) v1(58.42,89.53) v1(58.42,79.38) v1(58.42,71.75) v1(58.41,22.86) v1(58.41,21.21) v1(58.41,19.69) v1(58.41,18.16) v1(58.41,16.64) v1(58.41,15.11) v1(58.41,13.59) v1(58.67,88.15) v1(58.67,87.64) v1(58.67,87.13) v1(58.67,75.32) v1(58.67,74.82) v1(58.67,74.31) v1(59.18,88.15) v1(59.18,87.64) v1(59.18,87.13) v1(59.18,75.32) v1(59.18,74.82) v1(59.18,74.31) v1(59.43,35.94) v1(59.94,97.92) v1(60.07,33.78) v1(60.96,135.26) v1(60.96,132.72) v1(60.96,130.18) v1(60.96,127.64) v1(60.96,125.09) v1(60.96,122.55) v1(60.96,107.31) v1(60.96,102.23) v1(60.96,95.89) v1(60.96,71.75) v1(60.96,31.12) v1(60.96,28.58) v1(61.09,63.25) v1(62.1,43.94) v1(62.36,121.28) v1(63.5,135.26) v1(63.5,132.72) v1(63.5,130.18) v1(63.5,127.64) v1(63.5,125.09) v1(63.5,104.77) v1(63.5,102.23) v1(63.5,99.69) v1(64.14,5.84) v1(64.26,122.43) v1(65.09,14.16) v1(65.09,13.65) v1(65.09,13.14) v1(65.09,12.64) v1(65.98,121.6) v1(66.04,135.26) v1(66.04,132.72) v1(66.04,130.18) v1(66.04,127.64) v1(66.04,125.09) v1(66.04,115.82) v1(66.04,111.82) v1(66.04,102.23) v1(66.04,99.69) v1(66.04,43.81) v1(66.48,54.04) v1(67.06,56.52) v1(68.58,135.26) v1(68.58,132.72) v1(68.58,122.55) v1(68.58,60.96) v1(68.58,43.81) v1(68.58,41.27) v1(68.58,38.73) v1(70.1,36.07) v1(70.1,35.56) v1(70.1,35.06) v1(70.74,36.07) v1(70.74,35.56) v1(70.74,35.06) v1(70.87,56.64) v1(71.12,114.94) v1(71.12,112.39) v1(71.12,43.81) v1(71.12,41.27) v1(71.12,38.73) v1(73.41,17.65) v1(73.66,114.94) v1(73.66,112.39) v1(73.66,43.81) v1(73.66,41.27) v1(73.66,38.73) v1(73.66,36.2) v1(73.66,33.66) v1(73.66,31.12) v1(73.66,28.58) v1(73.66,26.03) v1(73.66,23.49) v1(73.66,20.95) v1(73.66,13.34) v1(73.66,10.79) v1(73.66,8.25) v1(73.66,5.71) v1(74.17,67.06) v1(75.95,85.47) v1(76.2,120.02) v1(76.2,114.94) v1(76.2,112.39) v1(76.2,107.31) v1(76.2,94.61) v1(76.2,28.58) v1(76.2,26.03) v1(76.2,23.49) v1(76.2,20.95) v1(76.2,18.41) v1(76.2,15.88) v1(76.2,13.34) v1(76.2,10.79) v1(76.2,8.25) v1(76.2,5.71) v1(78.74,135.26) v1(78.74,132.72) v1(78.74,122.55) v1(78.74,120.02) v1(78.74,117.47) v1(78.74,114.94) v1(78.74,112.39) v1(78.74,109.86) v1(78.74,107.31) v1(78.74,104.77) v1(78.74,97.16) v1(78.74,94.61) v1(78.74,48.59) v1(78.74,46.61) v1(78.74,43.81) v1(78.74,41.27) v1(78.74,36.2) v1(78.74,33.66) v1(78.74,31.12) v1(78.74,28.58) v1(78.74,26.03) v1(78.74,23.49) v1(78.74,20.95) v1(78.74,18.41) v1(78.74,15.88) v1(78.74,13.34) v1(78.74,10.79) v1(78.74,5.71) v1(81.28,130.18) v1(81.28,127.64) v1(81.28,125.09) v1(81.28,122.55) v1(81.28,120.02) v1(81.28,117.47) v1(81.28,114.94) v1(81.28,112.39) v1(81.28,109.86) v1(81.28,107.31) v1(81.28,104.77) v1(81.28,102.23) v1(81.28,99.69) v1(81.28,97.16) v1(81.28,94.61) v1(81.28,64.14) v1(81.28,61.59) v1(81.28,59.05) v1(81.28,56.52) v1(81.28,48.89) v1(81.28,46.35) v1(81.28,41.27) v1(81.28,38.73) v1(81.28,36.2) v1(81.28,33.66) v1(81.28,31.12) v1(81.28,28.58) v1(81.28,26.03) v1(81.28,23.49) v1(81.28,20.95) v1(81.28,18.41) v1(81.28,15.88) v1(81.28,13.34) v1(81.28,10.79) v1(83.82,127.64) v1(83.82,125.09) v1(83.82,122.55) v1(83.82,120.02) v1(83.82,117.47) v1(83.82,114.94) v1(83.82,112.39) v1(83.82,109.86) v1(83.82,107.31) v1(83.82,104.77) v1(83.82,102.23) v1(83.82,99.69) v1(83.82,97.16) v1(83.82,94.61) v1(83.82,48.89) v1(83.82,46.35) v1(83.82,41.27) v1(83.82,38.73) v1(83.82,36.2) v1(83.82,33.66) v1(83.82,31.12) v1(83.82,28.58) v1(83.82,26.03) v1(83.82,23.49) v1(83.82,20.95) v1(83.82,18.41) v1(83.82,15.88) v1(83.82,13.34) v1(83.82,10.79)
PGND: length 10
  TOP w0.635: TP4.1 69.97,1.59 68.36,1.59 R108.2 67.79,1.59 66.28,1.59 E15.2 65.86,1.65 P21.14 ; P21.13 45.37,1.65 E14.2
PGND1: length 10.1
  TOP w0.635: E13.2 43.4,1.65 P27.14 ; TP3.1 18.8,1.59 20.38,1.59 C87.1 21.03,1.59 22.38,1.59 E12.2 23.02,1.65 P27.13
VDD_3V3: length 55.2
  TOP w0.203: 63.82,85.72 U12.5 ; 63.76,90.42 U14.5 ; 20.08,94.45 U13.8
  TOP w0.254: C99.1 50.55,81.53 U10.18 ; v1(40.51,78.49) 40.51,78.87 40.67,79.03 U10.48 ; U10.39 41.88,83.53 v1(42.18,83.82) ; U10.36 42.24,87.42 C103.1 ; U10.34 43.24,87.43 C105.1
  TOP w0.508: v1(69.72,67.56) C135.1 U15.5 ; 9.78,54.65 TP1.1 ; TP1.1 9.78,58.42 8.76,59.44 R16.2 ; TP1.1 8.6,55.83 ; TP1.1 10.96,55.83 ; R134.2 v1(70.61,70.74) ; 63.76,90.42 C134.1 v1(63.76,92.45) ; R114.1 v1(53.98,105.79) ; R49.2 13.47,56.07 C132.2 ; 63.82,85.72 C133.1 v1(63.82,87.76) ; R115.1 v1(49.28,102.88) ; C110.2 v1(40.39,89.41) ; U9.5 C112.1 v1(69.72,72.39) ; E9.1 v1(73.28,83.95) ; 20.08,94.45 C73.1 v1(21.6,92.93) ; R129.2 v1(65.02,72.64) ; 65.56,39 E4.1 ; E4.1 66.28,39.75 ; E4.1 65.56,40.5 ; E10.2 v1(32,63.63) ; v1(51.82,81.79) 51.81,81.78 C99.1 ; R111.2 v1(39,90.8) ; C105.1 v1(43.44,88.38) ; R133.2 v1(60.07,91.19) ; R44.2 v1(46.23,73.53) ; R113.2 v1(60.85,77.23) ; C103.1 v1(42.03,88.38) ; R112.2 v1(53.4,82.03) ; R116.2 v1(55.12,105.79) ; R132.2 v1(60.07,82.83)
  L4_PWR w0.508: 8.6,55.83 TP1.1 ; TP1.1 10.96,55.83 ; TP1.1 9.78,54.65 ; TP1.1 9.78,57.02
  BOTTOM w0.508: v1(51.82,81.79) v1(51.31,81.79) 50.29,81.79 R39.2 ; R51.2 v1(73.02,60.96) ; C101.1 40.52,77.85 40.51,77.86 v1(40.51,78.49)
  vias: v1(7.49,55.75) v1(7.49,55.12) v1(8.13,55.75) v1(8.13,55.12) v1(11.43,56.39) v1(11.43,55.75) v1(11.43,55.12) v1(12.07,56.39) v1(12.07,55.75) v1(12.07,55.12) v1(38.73,88.15) v1(38.73,87.64) v1(38.73,87.13) v1(39.24,88.15) v1(39.24,87.64) v1(39.24,87.13) v1(51.18,88.13) v1(51.18,87.62) v1(51.18,87.11) v1(51.69,88.13) v1(51.69,87.62) v1(51.69,87.11) v1(55.8,78.87) v1(56.31,78.87) v1(59.63,22.54) v1(59.63,22.03) v1(60.13,22.54) v1(60.13,22.03) v1(66.91,40.51) v1(66.91,40) v1(66.91,39.5) v1(66.91,38.99) v1(67.42,40.51) v1(67.42,40) v1(67.42,39.5) v1(67.42,38.99)
VDD_5V: length 12.6
  TOP w0.508: C42.2 16.13,36.2 15.75,36.58 12.2,36.58 12.19,36.57 TP2.1
  BOTTOM w0.508: R142.1 54.73,10 55.4,10.67 57.91,10.67
  vias: v1(17.02,35.18) v1(17.02,34.67) v1(17.02,34.16) v1(17.53,35.18) v1(17.53,34.67) v1(17.53,34.16) v1(18.03,35.18) v1(18.03,34.67) v1(18.03,34.16) v1(58.99,12.48) v1(58.99,11.97) v1(58.99,11.47) v1(58.99,10.96) v1(61.4,22.54) v1(61.4,22.03) v1(61.91,22.54) v1(61.91,22.03)
VIN0: length 56.3
  TOP w0.203: R84.2 v1(23.44,115.76) ; U10.4 v1(43.74,78.87)
  BOTTOM w0.203: v1(23.44,115.76) 24.28,115.76 24.49,115.55 24.49,89.11 27.95,85.65 42.24,85.65 43.94,83.95 43.94,80 43.74,79.8 v1(43.74,78.87)
VIN1: length 68.6
  TOP w0.203: R73.2 v1(23.44,125.54) ; U10.2 v1(42.74,78.87)
  BOTTOM w0.203: v1(23.44,125.54) 24.69,125.54 24.89,125.34 24.89,89.31 28.14,86.05 42.41,86.05 44.35,84.12 44.35,78.68 43.97,78.31 43.3,78.31 v1(42.74,78.87)
AD243X_AN: length 21.7
  TOP w0.241: U7.28 43.2,48.42 arc(43.23,48.37) 43.25,48.31 43.25,47.84 arc(43.2,47.6) 43.06,47.41 39.1,43.44 arc(38.4,42.98) 37.58,42.81 35.23,42.81 arc(33.84,42.24) 33.26,40.84 33.26,38.23 arc(33.18,37.89) C24.1 33.26,37.33 33.26,34.37 33.02,34.13 L1.1
AD243X_AP: length 21.7
  TOP w0.241: U7.29 43.7,48.42 arc(43.67,48.37) 43.65,48.31 43.65,47.84 arc(43.58,47.46) 43.36,47.13 39.39,43.16 arc(38.56,42.6) 37.58,42.41 35.23,42.41 arc(34.12,41.95) 33.66,40.84 33.66,38.17 arc(33.74,37.86) C24.2 33.66,37.33 33.66,34.37 33.9,34.13 L2.1
AD243X_BCLK: length 82.4
  TOP w0.178: v1(50.81,105.29) R126.1 R127.1
  TOP w0.508: R10.1 v1(41.78,62.24) ; R67.2 v1(39.57,64.09)
  L3_PWR w0.178: P16.1 29.46,60.2 30.61,61.34 35.56,61.34 38.31,64.09 v1(39.57,64.09) 40.34,64.09 40.89,64.64 40.89,70.87 43.43,73.41 43.43,76.2 44.58,77.34 44.58,82.55 46.01,83.99 46.01,90.5 44.04,92.47 44.04,96.62 44.36,96.94 44.36,98.84 v1(50.81,105.29)
  L3_PWR w0.203: v1(41.78,62.24) 39.99,62.24 39.57,62.66 38.15,62.66 36.7,61.21 36.7,60.73 34.34,58.37 30.4,58.37 29.97,58.8 28.96,58.8 P16.1
  BOTTOM w0.203: R10.1 v1(41.78,62.24)
AD243X_BN: length 21.7
  TOP w0.241: U7.34 46.2,48.42 arc(46.16,48.37) 46.15,48.31 46.15,47.84 arc(46.2,47.6) 46.34,47.41 50.3,43.44 arc(51,42.98) 51.82,42.81 54.17,42.81 arc(55.56,42.24) 56.14,40.84 56.14,38.23 arc(56.22,37.89) C88.1 56.14,37.33 56.14,34.37 56.38,34.13 L11.1
AD243X_BP: length 21.7
  TOP w0.241: L10.1 55.49,34.13 55.74,34.37 55.74,37.33 C88.2 arc(55.66,37.89) 55.74,38.23 55.74,40.84 arc(55.28,41.95) 54.17,42.41 51.82,42.41 arc(50.84,42.6) 50.01,43.16 46.04,47.13 arc(45.82,47.46) 45.75,47.84 45.75,48.31 arc(45.73,48.37) 45.7,48.42 U7.33
AD243X_GPIO4: length 5.7
  TOP w0.178: U7.22 39.73,50.82 39.37,51.18 R13.1
AD243X_IOVDD: length 12
  TOP w0.203: v1(40,51.69) 40.38,51.32 U7.21
  TOP w0.254: U7.11 42.2,55.41 v1(41.91,55.12)
  TOP w0.508: v1(56.39,56.38) 56.39,56.39 v1(55.68,56.39) ; R138.2 v1(67.18,90.68) ; 55.68,57.02 v1(55.68,56.39) ; 55.68,57.02 v1(55.68,57.02) ; 55.68,57.02 v1(56.39,57.02) ; v1(55.68,56.39) 55.67,56.38 R18.1 ; R139.2 v1(67.18,85.98) ; R128.2 v1(22.61,51.69) ; R34.2 v1(22.61,49.02)
  BOTTOM w0.254: v1(40,51.69) 40.25,51.94 R43.1
  BOTTOM w0.508: C16.1 42.42,55.88 41.91,55.37 v1(41.91,55.12) 41.66,54.86 C15.1
  vias: v1(64.26,66.04) v1(64.26,65.53) v1(64.77,66.04) v1(64.77,65.53) v1(65.28,66.04) v1(65.28,65.53)
AD243X_IRQ: length 101.8
  TOP w0.178: DS2.A TP9.1 28.45,45.72 28.7,45.97 28.7,48.77 29.72,49.78 v1(33.78,49.78) R14.2 ; R117.2 v1(81.1,55.3)
  BOTTOM w0.178: v1(81.1,55.3) 80.52,54.72 80.52,50.55 81.91,49.15 81.91,47.88 79.63,45.59 66.75,45.59 66.37,45.97 66.37,46.69 63.5,49.56 63.5,62.01 61.5,64.01 50.8,64.01 49.98,63.19 37.16,63.19 36.43,62.46 36.43,53.62 37.73,52.31 37.73,51.07 36.45,49.78 v1(33.78,49.78)
AD243X_ISENSEP: length 37.6
  TOP w0.254: v1(49.77,51.67) 49.77,51.8 49.25,52.32 U7.42
  BOTTOM w0.406: 66.52,28.07 66.52,31.4 64.01,33.91 64.01,45.73 58.68,51.05 51.77,51.05 51.15,51.67 v1(49.77,51.67)
AD243X_MISO: length 56.6
  TOP w0.178: R79.2 v1(66.55,52.76) ; R21.2 v1(33.78,54.86)
  BOTTOM w0.178: v1(33.78,54.86) 34.29,55.37 34.29,55.78 34.3,55.79 34.3,57.52 33.08,58.74 33.08,60.9 34.29,62.1 34.29,64.59 35.49,65.8 62.98,65.8 65.46,63.32 65.46,52.94 65.63,52.76 v1(66.55,52.76)
AD243X_MOSI: length 72.1
  TOP w0.178: R22.2 v1(33.78,53.72) ; v1(80.39,49.15) 80.38,49.16 R81.2
  BOTTOM w0.178: v1(80.39,49.15) 66.67,49.15 64.69,51.13 64.69,62.82 62.48,65.04 35.95,65.04 35.18,64.27 35.18,54.61 34.29,53.72 v1(33.78,53.72)
AD243X_RESET: length 43
  TOP w0.178: U7.25 41.7,49.61 41.72,49.64 41.72,49.98 v1(41.91,50.16) ; R76.2 v1(59.89,63.12)
  BOTTOM w0.178: v1(41.91,50.16) 41.91,50.3 42.29,50.68 C17.2 41.04,50.96 R43.2 38.73,50.93 38.35,51.31 38.35,52.32 36.81,53.87 36.81,62.21 37.36,62.76 57.56,62.76 58.29,63.5 59.51,63.5 v1(59.89,63.12)
AD243X_SCK: length 61
  TOP w0.178: R23.2 v1(33.78,52.58) ; R80.2 v1(66.55,50.22)
  BOTTOM w0.178: v1(66.55,50.22) 65.07,51.69 65.07,63.01 62.67,65.42 35.75,65.42 34.8,64.46 34.8,54.86 34.21,54.28 32.89,54.28 32.71,54.1 32.71,52.76 32.89,52.58 v1(33.78,52.58)
AD243X_SCL: length 82.8
  TOP w0.203: R25.2 v1(72.64,81.53) ; R137.1 R138.1 v1(68.07,89.01) ; v1(33.78,56.01) R20.2
  BOTTOM w0.203: v1(72.64,81.53) 74.04,82.93 74.04,86.61 73.33,87.33 71.68,87.33 69.99,89.01 v1(68.07,89.01) 66.66,89.01 66.17,88.52 66.17,68.7 64.57,67.1 63.74,67.1 63.25,66.6 35.16,66.6 33.49,64.93 33.49,62.57 32.09,61.18 32.09,57.7 v1(33.78,56.01)
AD243X_SDA: length 68.2
  TOP w0.203: v1(68.07,84.31) R139.1 R136.1 ; R19.2 v1(33.78,57.24) ; R30.2 v1(72.77,82.8)
  BOTTOM w0.203: v1(33.78,57.24) 32.64,58.38 32.64,61.09 33.9,62.34 33.9,64.76 35.33,66.19 63.41,66.19 63.91,66.69 64.74,66.69 66.61,68.57 66.61,82.85 v1(68.07,84.31) 71.26,84.31 v1(72.77,82.8)
AD243X_SIO2: length 67.5
  TOP w0.178: R8.2 v1(44.07,59.94) 44.2,59.81 U7.7 ; R125.2 v1(81.1,52.76)
  BOTTOM w0.178: v1(81.1,52.76) 81.1,50.6 82.42,49.28 82.42,46.36 81.16,45.09 66.49,45.09 65.99,45.59 65.99,46.53 63.12,49.4 63.12,61.59 62.4,62.32 47.08,62.32 45.59,60.83 44.25,60.83 44.07,60.66 v1(44.07,59.94)
AD243X_SWP: length 42.6
  TOP w0.254: v1(49.06,51.71) 49,51.71 48.89,51.82 U7.41
  BOTTOM w0.406: R98.1 63.32,21.95 63.32,45.52 58.39,50.44 51.52,50.44 51.04,50.93 49.62,50.93 49.06,51.49 v1(49.06,51.71)
AD243X_SYNC: length 60.5
  TOP w0.178: v1(45.74,78.75) U10.8 ; v1(47.5,80.53) U10.16 ; R120.1 v1(53.21,108.97)
  TOP w0.508: R9.1 v1(42.93,62.24) ; R69.2 v1(44.65,64.09)
  L3_PWR w0.178: v1(53.21,108.97) 53.21,108.21 53.38,108.04 53.38,105.56 53.21,105.4 53.21,102.74 49.03,98.56 49.03,82.06 v1(47.5,80.53) 47.5,80.51 v1(45.74,78.75) 45.74,77.83 46.1,77.47 47.62,77.47 49.02,76.07 49.02,73.91 45.85,70.74 45.85,65.29 v1(44.65,64.09) 44.31,63.75 43.31,63.75 42.93,63.37 v1(42.93,62.24)
  BOTTOM w0.178: R9.1 v1(42.93,62.24)
AD243X_VBUS: length 66.5
  TOP w0.254: 48.85,52.9 48.77,52.82 U7.43 ; v1(49.62,114.94) 49.66,114.94 49.96,115.24 A2.20 ; A2.14 53.07,117.11 v1(52.83,117.35) ; v1(55.12,114.94) 54.92,114.74 A2.10
  TOP w0.508: v1(55.12,114.94) v1(55.63,114.94) ; R1.2 v1(17.96,39.69) ; R24.2 v1(8.76,14.61) ; 48.85,52.9 v1(49.03,53.08) ; v1(52.83,117.35) v1(52.83,117.86) ; v1(49.62,114.94) v1(49.11,114.94)
  L3_PWR w0.508: P27.11 37.62,10.76 ; P27.11 37.62,8.44 ; P27.11 38.78,9.6 ; 35.7,7.38 P27.7 36.76,6.33 ; 30.6,3.5 P27.2 29.55,4.55 ; P27.3 31.62,7.38
  L3_PWR w0.635: P27.3 30.6,5.31 P27.2
  L4_PWR w0.508: 30.6,3.5 P27.2 29.55,4.55 ; P27.3 31.62,7.38 ; P27.11 37.62,10.76 ; P27.11 37.62,8.44 ; P27.11 36.47,9.6 ; P27.11 38.78,9.6 ; 35.7,7.38 P27.7 36.76,6.33
  BOTTOM w0.406: 69.12,28.07 69.12,30.58 64.64,35.05 64.64,45.96 58.94,51.66 52.1,51.66 51.45,52.31 49.79,52.31 v1(49.03,53.08)
  vias: v1(8.51,25.65) v1(8.51,24.89) v1(9.27,25.65) v1(9.27,24.89) v1(10.92,38.23) v1(10.92,37.72) v1(11.43,38.23) v1(11.43,37.72) v1(11.94,38.23) v1(11.94,37.72) v1(70.1,28.58) v1(70.1,28.07) v1(70.1,27.56) v1(70.23,14.73) v1(70.23,14.22) v1(70.23,13.72) v1(70.23,13.21) v1(70.74,28.58) v1(70.74,28.07) v1(70.74,27.56) v1(70.74,14.73) v1(70.74,14.22) v1(70.74,13.72) v1(70.74,13.21) v1(71.25,14.73) v1(71.25,14.22) v1(71.25,13.72) v1(71.25,13.21)
AD243X_VIN: length 8.8
  TOP w0.254: U7.46 v1(47.12,54.32)
  TOP w0.508: C12.2 55.5,58.17 56.52,59.18 56.52,60.58 57.02,61.09 P8.1
  BOTTOM w0.508: C14.1 C13.1 46.23,54.83 46.74,54.32 v1(47.12,54.32)
  vias: v1(23.61,12.04) v1(23.61,11.53) v1(24.12,12.04) v1(24.12,11.53) v1(52.83,58.67) v1(52.83,58.17) v1(52.83,57.66)
AD243X_VOUT2: length 58.5
  TOP w0.203: U7.45 48.54,53.82 v1(48.64,53.72) ; DS3.A 61.57,50.19 59.31,52.45 59.31,54.74 P15.1
  TOP w0.508: R29.2 v1(9.91,14.61) ; E17.1 v1(73.41,76.45) ; v1(48.64,53.72) 48.89,53.98 49.53,53.98 ; P15.1 56.9,55.38 R18.2
  BOTTOM w0.203: v1(27.69,42.93) 23.11,42.93 14.35,34.16 14.35,23.49 12.32,21.46 12.32,17.02 v1(9.91,14.61)
  BOTTOM w0.508: v1(48.64,53.72) 48.02,53.72 C19.1
  vias: v1(54.99,54.61) v1(54.99,54.1) v1(55.5,54.61) v1(55.5,54.1)
AD243X_VSENSEP: length 48.1
  TOP w0.254: U7.40 48.63,51.32 48.78,51.17 50.91,51.17 52.15,52.4 v1(52.58,52.4)
  BOTTOM w0.406: v1(52.58,52.4) 52.65,52.32 59.31,52.32 65.36,46.27 65.36,35.99 71.75,29.59 R99.1
ADAU1701_BCLK: length 33.5
  TOP w0.178: v1(46.35,80.14) 46.35,78.48 46.24,78.37 U10.9 ; R126.2 v1(51.81,105.28)
  TOP w0.203: v1(46.61,82.04) 46.62,82.03 U10.19
  L3_PWR w0.178: v1(46.35,80.14) 46.35,80.99 46.61,81.24 v1(46.61,82.04) 46.61,98.18 51.81,103.38 v1(51.81,105.28)
ADAU1701_I2C_EN*: length 57.9
  TOP w0.203: U15.2 v1(67.82,65.15) ; v1(61.02,85.85) 61.26,85.61 U12.1 ; v1(60.96,90.55) 61.2,90.31 U14.1 ; U9.4 R134.1 v1(70.61,68.07)
  BOTTOM w0.203: v1(67.82,65.15) 69.22,65.15 70.61,66.55 v1(70.61,68.07) 70.61,68.45 68.61,70.46 68.61,75.46 71.5,78.36 73.15,78.36 75.34,80.54 75.34,87.86 73.63,89.56 72.62,89.56 70.38,91.8 65.32,91.8 64.2,90.68 61.09,90.68 v1(60.96,90.55) 60.22,89.81 60.22,85.75 60.43,85.54 60.71,85.54 v1(61.02,85.85)
ADAU1701_SCL: length 31.3
  TOP w0.203: U10.23 52.53,84.03 53.61,85.11 58.18,85.11 60.07,87 R133.1 60.86,89.31 v1(60.96,89.41) 61.21,89.66 U14.2 ; R61.2 v1(72.77,89.03)
  BOTTOM w0.203: v1(72.77,89.03) 72.26,89.03 69.9,91.39 65.49,91.39 64.37,90.27 61.82,90.27 v1(60.96,89.41)
ADAU1701_SDA: length 35.5
  TOP w0.203: U12.2 61.28,84.96 v1(61.02,84.71) 61.02,84.7 R132.1 53.84,84.7 52.67,83.53 U10.22 ; R62.2 v1(72.77,90.3)
  BOTTOM w0.203: v1(72.77,90.3) 70.87,92.2 65.15,92.2 64.03,91.08 60.73,91.08 59.82,90.17 59.82,85.29 60.02,85.09 60.64,85.09 v1(61.02,84.71)
ADAU1701_SDATA_IN: length 29.1
  TOP w0.178: v1(47.62,76.2) 47.24,76.58 U10.11 ; C3.2 v1(33.78,58.93) R12.1
  TOP w0.508: R68.2 v1(42.11,64.09)
  L3_PWR w0.178: v1(33.78,58.93) 38.23,63.37 41.39,63.37 v1(42.11,64.09) 43.43,65.42 43.43,70.74 44.83,72.14 46.35,72.14 47.62,73.41 v1(47.62,76.2)
ADAU1701_SDATA_OUT: length 49.9
  TOP w0.203: v1(41.4,72.39) 47.5,72.39 49.1,73.99 49.1,76.15 49.66,76.71 51.82,76.71 52.58,77.47 R110.1
  TOP w0.508: R66.2 v1(37.03,64.1)
  L3_PWR w0.203: P4.3 21.66,64.14 27.81,64.14 29.84,62.1 35.04,62.1 v1(37.03,64.1) 37.03,65.46 35.69,66.8 35.69,71.81 35.9,72.02 39,72.02 39.37,72.39 v1(41.4,72.39)
ADAU1701_SELFBOOT: length 36.9
  TOP w0.203: v1(44.74,75.95) U10.6 ; U9.2 v1(65.02,69.98) ; R5.2 P22.2
  BOTTOM w0.203: v1(65.02,69.98) 64.14,69.98 63.56,70.55 63.56,73.34 P22.2 64.39,75.44 63.88,75.95 57.6,75.95 54.5,72.85 49.73,72.85 49,72.11 46.25,72.11 44.74,73.62 v1(44.74,75.95)
ADAU1701_WP*: length 41.5
  TOP w0.203: U10.21 v1(48.04,83.03) ; A1.7 70.74,87.76 69.22,86.23 69.22,80.77 68.26,79.82 P18.1
  BOTTOM w0.203: v1(48.04,83.03) 48.04,82.29 48.29,82.04 49.02,82.04 R39.1 49.28,79.75 51.66,77.37 59.97,77.37 60.61,78.01 62.58,78.01 P18.1
